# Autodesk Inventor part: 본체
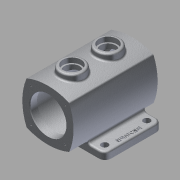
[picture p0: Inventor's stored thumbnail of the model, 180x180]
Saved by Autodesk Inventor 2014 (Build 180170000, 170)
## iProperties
Created: 2013-02
Part Number: 본체
Document SubType Name: Modeling
Designer: 한국산업디자인학원[gmhk.co.kr]
Density: 2.71 g/cm^3
Material: 알루미늄 6061
Appearance: _시험_알루미늄 표면거칠기
Mass: 1212.6 g
Surface Area: 1019.31 cm^2
Volume: 447.452 cm^3
Author: 한국산업디자인학원[gmhk.co.kr]
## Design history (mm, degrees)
sketch "스케치1"
  geometry: L1 (-65, 55)-(65, 55); L2 (65, 55)-(65, -40); L3 (65, -40)-(-65, -40); L4 (-65, -40)-(-65, 55); 2 further points
  constraints: 8 end point, 2 parallel, 1 horizontal, 1 midpoint, 1 perpendicular, 1 vertical alignment
  dimensions: "d0" = 130 distance of L2.end L3.end; "d1" = 95 distance of L1.end L2.end; "d47" = 40 distance from line of L3 point (0, 0)
extrude "돌출1" new body sketch "스케치1" distance "d2" = 12; taper "d3" = 0 deg
sketch "스케치2"
  geometry: L1 (-35.355, 85.355)-(35.355, 85.355); L2 (35.355, 85.355)-(35.355, 14.645); L3 (35.355, 14.645)-(-35.355, 14.645); L4 (-35.355, 14.645)-(-35.355, 85.355); L5 (35.355, 85.355)-(-35.355, 14.645); L6 (65, 0)-(-65, 0) reference; A1 r 91.05 centre (0, 1.45) between (35.355, 85.355) and (-35.355, 85.355); A2 r 91.05 centre (-48.55, 50) between (35.355, 14.645) and (35.355, 85.355); A3 r 91.05 centre (0, 98.55) between (-35.355, 14.645) and (35.355, 14.645); A4 r 91.05 centre (48.55, 50) between (-35.355, 85.355) and (-35.355, 14.645); 3 further points
  constraints: 10 end point, 8 point on circle, 4 centre point, 3 equal radius, 2 midpoint, 2 parallel, 2 perpendicular, 1 horizontal, 1 vertical alignment
  dimensions: "d4" = 50 distance from line of point (0, 50) L6; "d5" = 50 distance of L1.start point (0, 50); "d6" = 85 dimension on A2 A4
extrude "돌출2" join sketch "스케치2" stored distance "d7" = 140; taper "d8" = 0 deg
sketch "스케치3"
  geometry: L1 (28.27, 12)-(65, 12) reference; L2 (-65, 12)-(-28.27, 12) reference; A1 r 91.05 centre (0, 98.55) between (-35.355, 14.645) and (35.355, 14.645) reference; A2 r 91.05 centre (48.55, 50) between (-35.355, 85.355) and (-35.355, 14.645) reference; A3 r 91.05 centre (-48.55, 50) between (35.355, 14.645) and (35.355, 85.355) reference; A4 r 5 centre (-41.653, 17) between (-41.653, 12) and (-36.957, 18.718); A5 r 5 centre (41.653, 17) between (36.957, 18.718) and (41.653, 12); 1 further point
  constraints: 6 point on circle, 4 tangent, 2 centre point, 2 point on line, 1 equal radius
  dimensions: "d9" = 5 radius of A5
extrude "돌출3" join sketch "스케치3" stored distance "d10" = 120; taper "d11" = 0 deg
fillet "모깎기1" dims "d12" = 3
fillet "모깎기2" dims "d13" = 10
fillet "모깎기3" dims "d14" = 3
sketch "스케치4"
  geometry: L1 (-70, 84.185)-(-70, 85.839) reference; L2 (-70, 15.815)-(-70, 84.185) reference; L3 (-70, 14.161)-(-70, 15.815) reference; L4 (-70, 14.161)-(-70, 14.161) reference; L5 (-70, 15.815)-(-70, 14.161) reference; L6 (-70, 84.185)-(-70, 15.815) reference; L7 (-70, 85.839)-(-70, 84.185) reference; L8 (-70, 85.839)-(-70, 85.839) reference; L9 (70, 15.815)-(70, 14.161) reference; L10 (70, 84.185)-(70, 15.815) reference; L11 (70, 85.839)-(70, 84.185) reference; L12 (70, 85.839)-(70, 85.839) reference; L13 (70, 84.185)-(70, 85.839) reference; L14 (70, 15.815)-(70, 84.185) reference; L15 (70, 14.161)-(70, 15.815) reference; L16 (70, 14.161)-(70, 14.161) reference; L17 (-70, 50)-(70, 50); L18 (-70, 80)-(-58, 80); L19 (-58, 80)-(-58, 87.5); L20 (-58, 87.5)-(58, 87.5); L21 (58, 87.5)-(58, 80); L22 (58, 80)-(70, 80); 1 further point
  constraints: 12 end point, 2 collinear, 2 midpoint, 2 parallel, 2 perpendicular, 2 point on line
  dimensions: "d15" = 60 diameter of L18 L17; "d16" = 75 diameter of L20 L17; "d17" = 12 distance of L18.start L18.end; "d18" = 12 distance of L21.end L22.end
revolve "회전1" sketch "스케치4" stored, may be unused: angle "d19" = 90 deg
fillet "모깎기4" dims "d20" = 3
node "작업 평면2"
  node "작업 평면1"
sketch "스케치5"
  geometry: C1 r 20 at (0, 30); C2 r 20 at (0, -30); 1 further point
  constraints: 2 centre point, 2 vertical alignment
  dimensions: "d22" = 40 diameter of C1; "d23" = 40 diameter of C2; "d24" = 60 distance of C2.centre C1.centre; "d25" = 30 distance of point (0, 0) C1.centre (= 0.5 x d24)
extrude "돌출4" join sketch "스케치5" stored distance "d26" = 120; taper "d27" = 0 deg
fillet "모깎기5" dims "d28" = 3
hole "구멍1" diameter "d31" = 25; stored, may be unused: countersink angle "d35" = 90 deg, drill point angle "d37" = 118 deg; dims "d29" = 10, "d30" = 10, "d32" = 6, "d33" = 30, "d34" = 8, "d36" = 8
hole "구멍2" diameter "d40" = 25; stored, may be unused: countersink angle "d44" = 90 deg, drill point angle "d46" = 118 deg; dims "d38" = 10, "d39" = 10, "d41" = 6, "d42" = 30, "d43" = 8, "d45" = 8
sketch "스케치6"
  geometry: L1 (65, -30)-(65, 45) reference; 4 further points
  constraints: 1 midpoint, 1 vertical alignment
  dimensions: "d48" = 13 distance from line of point (52, 42.5) L1; "d49" = 70 distance of point (52, -27.5) point (52, 42.5); "d50" = 35 vertical distance of point (65, 7.5) point (52, 42.5) (= 0.5 x d49)
hole "구멍3" sketch "스케치6" at (52, -27.5), (52, 42.5) diameter "d51" = 11; stored, may be unused: countersink angle "d55" = 90 deg, drill point angle "d57" = 118 deg; dims "d52" = 6, "d53" = 30, "d54" = 8, "d56" = 8
sketch "스케치8"
  geometry: L1 (65, -30)-(65, 45) reference; 3 further points
  constraints: 1 horizontal alignment, 1 midpoint, 1 other
  dimensions: "d60" = 8 distance from line of point (57, 7.5) L1
feature "엠보싱2" sketch "스케치8" dims "d0" = 130, "d1" = 95, "d47" = 40, "d61" = 1, "d62" = 0
chamfer "모따기1" distance "d63" = 1; stored, may be unused: second distance "d64" = 2, angle "d65" = 45 deg
sketch "스케치9" dims "d9" = 5, "d75" = 40, "d76" = 360 deg
  geometry: L1 (0, 81)-(0, 50); L2 (0, 50)-(28.284, 78.284); 1 further point
  constraints: 4 end point, 1 vertical, 1 vertical alignment, 1 other
  dimensions: "d66" = 45 deg angle of L2 L1; "d67" = 40 distance of L2.end L1.end
hole "구멍4" sketch "스케치9" at (28.284, 78.284) diameter "d68" = 3.242; stored, may be unused: countersink angle "d72" = 90 deg, drill point angle "d74" = 118 deg; dims "d69" = 8, "d70" = 30, "d71" = 8, "d73" = 10
node "솔리드1"
mirror "대칭1"
pattern_circular "원형 패턴1" dims angle "d76" = 360 deg
mirror "대칭2"
node "투영된 루프1"
node "투영된 루프2"
